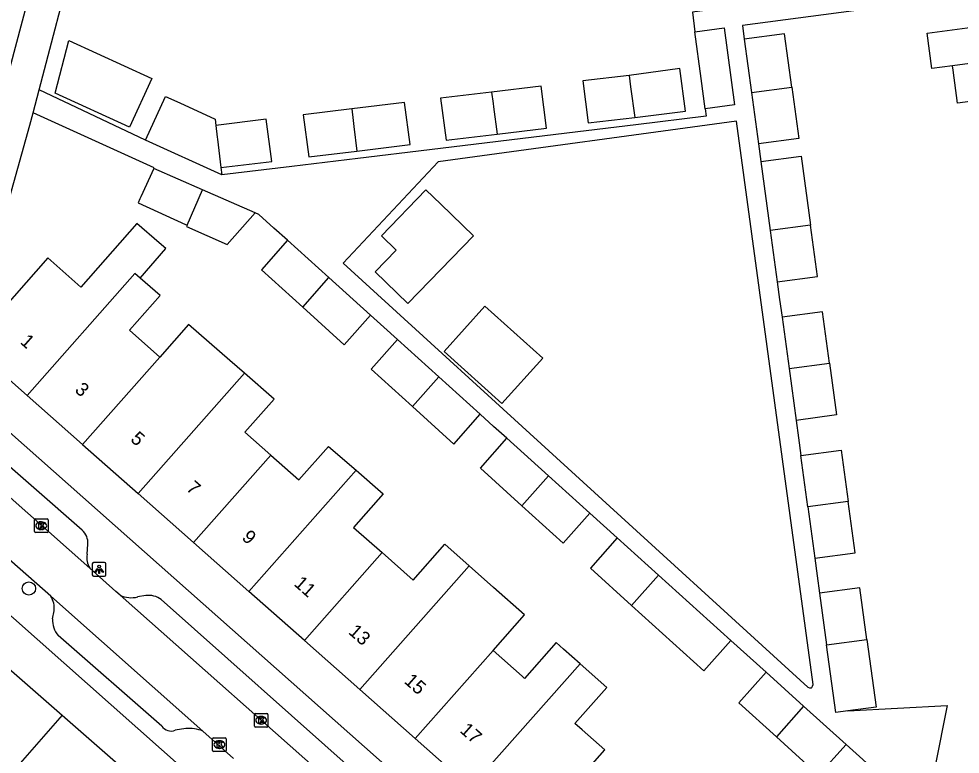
# Model space of a CAD drawing. Extents: x 163150 to 163546, y 380933 to 381635.
# Drawn here: x 163352.4 to 163421.5, y 381091.7 to 381145.6 of the extents above; entities that cross this region are included whole.
import ezdxf

# ---------------------------------------------------------------- set-up
doc = ezdxf.new("R2010")
doc.units = 0
for name, color, linetype in [('IMGEO_Boom', 7, 'Continuous'), ('IMGEO_Erf', 7, 'Continuous'), ('IMGEO_Kolk', 7, 'Continuous'), ('IMGEO_Lichtpunt', 7, 'Continuous'), ('IMGEO_Pand', 7, 'Continuous'), ('IMGEO_Pand_nummerreeks', 7, 'Continuous'), ('IMGEO_Rijbaan_lokaal_open', 7, 'Continuous'), ('IMGEO_Voetpad_open', 7, 'Continuous')]:
    doc.layers.add(name, color=color, linetype=linetype)

msp = doc.modelspace()

# ---------------------------------------------------------------- linework, layer by layer
at = {"layer": 'IMGEO_Boom'}
msp.add_circle((163353.157, 381103.826), 0.489, dxfattribs=at)
at = {"layer": 'IMGEO_Erf'}
msp.add_lwpolyline([(163402.808, 381139.036), (163402.509, 381141.274), (163402.053, 381144.689)], dxfattribs=at)
at = {"layer": 'IMGEO_Kolk'}
for p, q in [((163353.559, 381108.013), (163353.559, 381108.865)), ((163353.634, 381108.939), (163354.486, 381108.939)), ((163354.047, 381108.719), (163354.072, 381108.719)), ((163354.56, 381108.865), (163354.56, 381108.013)), ((163354.486, 381107.939), (163353.634, 381107.939)), ((163354.07, 381108.159), (163354.045, 381108.159)), ((163369.707, 381093.727), (163369.707, 381094.579)), ((163369.782, 381094.653), (163370.634, 381094.653)), ((163370.708, 381094.579), (163370.708, 381093.727)), ((163370.218, 381093.873), (163370.193, 381093.873)), ((163370.195, 381094.433), (163370.22, 381094.433)), ((163370.634, 381093.653), (163369.782, 381093.653)), ((163366.644, 381091.941), (163366.644, 381092.793)), ((163366.719, 381092.867), (163367.571, 381092.867)), ((163367.132, 381092.647), (163367.157, 381092.647)), ((163367.645, 381092.793), (163367.645, 381091.941)), ((163367.571, 381091.867), (163366.719, 381091.867)), ((163367.155, 381092.087), (163367.13, 381092.087))]:
    msp.add_line(p, q, dxfattribs=at)
for points in [[(163353.559, 381108.013), (163353.559, 381108.865)], [(163353.634, 381108.939), (163354.486, 381108.939)], [(163353.88, 381108.639), (163354.003, 381108.639), (163354.003, 381108.488), (163354.133, 381108.639), (163354.297, 381108.639), (163354.151, 381108.488), (163354.304, 381108.239), (163354.152, 381108.239), (163354.067, 381108.403), (163354.003, 381108.336), (163354.003, 381108.239), (163353.88, 381108.239), (163353.88, 381108.639)], [(163354.56, 381108.865), (163354.56, 381108.013)], [(163354.486, 381107.939), (163353.634, 381107.939)], [(163369.707, 381093.727), (163369.707, 381094.579)], [(163369.782, 381094.653), (163370.634, 381094.653)], [(163370.708, 381094.579), (163370.708, 381093.727)], [(163370.028, 381094.353), (163370.151, 381094.353), (163370.151, 381094.202), (163370.281, 381094.353), (163370.445, 381094.353), (163370.299, 381094.202), (163370.452, 381093.953), (163370.3, 381093.953), (163370.215, 381094.117), (163370.151, 381094.05), (163370.151, 381093.953), (163370.028, 381093.953), (163370.028, 381094.353)], [(163370.634, 381093.653), (163369.782, 381093.653)], [(163366.644, 381091.941), (163366.644, 381092.793)], [(163366.719, 381092.867), (163367.571, 381092.867)], [(163366.965, 381092.567), (163367.088, 381092.567), (163367.088, 381092.416), (163367.218, 381092.567), (163367.382, 381092.567), (163367.236, 381092.416), (163367.389, 381092.167), (163367.237, 381092.167), (163367.152, 381092.331), (163367.088, 381092.264), (163367.088, 381092.167), (163366.965, 381092.167), (163366.965, 381092.567)], [(163367.645, 381092.793), (163367.645, 381091.941)], [(163367.571, 381091.867), (163366.719, 381091.867)]]:
    msp.add_lwpolyline(points, dxfattribs=at)
for centre, start, end in [((163353.636, 381108.863), 91.55205, 178.44795), ((163353.636, 381108.863), 91.55205, 178.44795), ((163354.484, 381108.863), 1.55205, 88.44795), ((163354.484, 381108.863), 1.55205, 88.44795), ((163353.636, 381108.015), 181.55205, 268.44795), ((163353.636, 381108.015), 181.55205, 268.44795), ((163354.484, 381108.015), 271.55205, 358.44795), ((163354.484, 381108.015), 271.55205, 358.44795), ((163369.784, 381094.577), 91.55205, 178.44795), ((163369.784, 381094.577), 91.55205, 178.44795), ((163370.632, 381094.577), 1.55205, 88.44795), ((163370.632, 381094.577), 1.55205, 88.44795), ((163369.784, 381093.729), 181.55205, 268.44795), ((163369.784, 381093.729), 181.55205, 268.44795), ((163370.632, 381093.729), 271.55205, 358.44795), ((163370.632, 381093.729), 271.55205, 358.44795), ((163366.721, 381092.791), 91.55205, 178.44795), ((163366.721, 381092.791), 91.55205, 178.44795), ((163367.569, 381092.791), 1.55205, 88.44795), ((163367.569, 381092.791), 1.55205, 88.44795), ((163366.721, 381091.943), 181.55205, 268.44795), ((163366.721, 381091.943), 181.55205, 268.44795), ((163367.569, 381091.943), 271.55205, 358.44795), ((163367.569, 381091.943), 271.55205, 358.44795)]:
    msp.add_arc(centre, 0.0765, start, end, dxfattribs=at)
for centre, major_axis, ratio, start_param, end_param in [((163354.046, 381108.439), (-0.387, 0.002), 0.722429, 4.712389, 7.853982), ((163354.071, 381108.439), (-0.39, 0.002), 0.717154, 1.570796, 4.712389), ((163370.194, 381094.153), (-0.387, 0.002), 0.722429, 4.712389, 7.853982), ((163370.219, 381094.153), (-0.39, 0.002), 0.717154, 1.570796, 4.712389), ((163367.131, 381092.367), (-0.387, 0.002), 0.722429, 4.712389, 7.853982), ((163367.156, 381092.367), (-0.39, 0.002), 0.717154, 1.570796, 4.712389)]:
    msp.add_ellipse(centre, major_axis=major_axis, ratio=ratio, start_param=start_param, end_param=end_param, dxfattribs=at)
at = {"layer": 'IMGEO_Lichtpunt'}
for p, q in [((163357.812, 381105.637), (163357.812, 381104.83)), ((163357.812, 381105.637), (163357.812, 381104.83)), ((163358.714, 381105.732), (163357.906, 381105.732)), ((163358.714, 381105.732), (163357.906, 381105.732)), ((163358.808, 381104.83), (163358.808, 381105.637)), ((163358.808, 381104.83), (163358.808, 381105.637)), ((163357.906, 381104.736), (163358.714, 381104.736)), ((163357.906, 381104.736), (163358.714, 381104.736))]:
    msp.add_line(p, q, dxfattribs=at)
for points in [[(163358.186, 381105.301), (163358.225, 381105.273), (163358.037, 381105.011), (163357.999, 381105.038), (163358.186, 381105.301)], [(163358.288, 381105.253), (163358.335, 381105.253), (163358.335, 381104.931), (163358.288, 381104.931), (163358.288, 381105.253)], [(163358.398, 381105.273), (163358.436, 381105.3), (163358.623, 381105.038), (163358.584, 381105.01), (163358.398, 381105.273)]]:
    msp.add_lwpolyline(points, dxfattribs=at)
msp.add_circle((163358.311, 381105.435), 0.0994, dxfattribs=at)
for centre, start, end in [((163357.906, 381105.637), 90, 180), ((163357.906, 381105.637), 90, 180), ((163358.714, 381105.637), 0, 90), ((163358.714, 381105.637), 0, 90), ((163357.906, 381104.83), 180, 270), ((163357.906, 381104.83), 180, 270), ((163358.714, 381104.83), 270, 0), ((163358.714, 381104.83), 270, 360)]:
    msp.add_arc(centre, 0.0946, start, end, dxfattribs=at)
at = {"layer": 'IMGEO_Pand'}
for points in [[(163420.967, 381142.206), (163419.434, 381142.002), (163419.089, 381144.589), (163423.136, 381145.127), (163422.826, 381147.461)], [(163409.161, 381140.634), (163408.63, 381144.542), (163405.672, 381144.14)], [(163362.192, 381141.257), (163360.544, 381137.68), (163355.083, 381140.179), (163356.085, 381144.052), (163362.192, 381141.257)], [(163405.672, 381144.14), (163406.202, 381140.24)], [(163430.741, 381143.69), (163430.765, 381143.51), (163420.967, 381142.206)], [(163425.72, 381137.678), (163425.411, 381140.001), (163421.332, 381139.458), (163421.009, 381141.888), (163420.967, 381142.206)], [(163397.215, 381141.495), (163393.81, 381141.082), (163394.223, 381137.998), (163397.627, 381138.411)], [(163397.627, 381138.411), (163401.359, 381138.863), (163400.941, 381141.993), (163397.215, 381141.495)], [(163397.215, 381141.495), (163397.328, 381140.647), (163397.627, 381138.411)], [(163387.119, 381140.272), (163383.37, 381139.818), (163383.781, 381136.733), (163387.531, 381137.187)], [(163387.531, 381137.187), (163391.161, 381137.627), (163390.749, 381140.711), (163387.119, 381140.272)], [(163387.119, 381140.272), (163387.232, 381139.424), (163387.262, 381139.196), (163387.531, 381137.187)], [(163406.202, 381140.24), (163409.161, 381140.634)], [(163406.202, 381140.24), (163406.716, 381136.46)], [(163409.161, 381140.634), (163409.675, 381136.854), (163406.716, 381136.46)], [(163361.726, 381136.744), (163363.192, 381139.945), (163364.229, 381139.47), (163366.829, 381138.28), (163366.88, 381137.821)], [(163377.227, 381135.938), (163381.148, 381136.414), (163380.737, 381139.499), (163376.853, 381139.028)], [(163376.853, 381139.028), (163373.291, 381138.597), (163373.703, 381135.511), (163377.227, 381135.938)], [(163376.853, 381139.028), (163376.956, 381138.179), (163377.008, 381137.748), (163377.227, 381135.938)], [(163367.244, 381134.728), (163370.985, 381135.182), (163370.574, 381138.268), (163366.88, 381137.821)], [(163366.88, 381137.821), (163366.975, 381136.97), (163366.993, 381136.804), (163367.244, 381134.728)], [(163367.309, 381134.19), (163361.726, 381136.744)], [(163406.891, 381135.17), (163409.85, 381135.564), (163410.538, 381130.497)], [(163362.332, 381134.664), (163361.378, 381132.572), (163361.311, 381132.426), (163361.177, 381132.131), (163364.663, 381130.54), (163364.767, 381130.493)], [(163365.908, 381133.097), (163362.332, 381134.664)], [(163367.244, 381134.728), (163367.309, 381134.19)], [(163406.891, 381135.17), (163407.579, 381130.103)], [(163364.767, 381130.493), (163365.908, 381133.097)], [(163369.771, 381131.404), (163365.908, 381133.097)], [(163380.971, 381124.745), (163378.57, 381127.072), (163380.121, 381128.672), (163379.036, 381129.725), (163382.304, 381133.096), (163383.39, 381132.043), (163385.791, 381129.715), (163380.971, 381124.745)], [(163364.767, 381130.493), (163364.725, 381130.398), (163367.72, 381129.084), (163369.771, 381131.404)], [(163361.33, 381126.6), (163363.22, 381128.774), (163362.727, 381129.202), (163361.089, 381130.626), (163356.961, 381125.957), (163354.549, 381128.09), (163348.873, 381121.67), (163353.033, 381117.992)], [(163410.538, 381130.497), (163407.579, 381130.103)], [(163408.091, 381126.332), (163411.05, 381126.726), (163410.538, 381130.497)], [(163407.579, 381130.103), (163408.091, 381126.332)], [(163372.142, 381129.385), (163370.238, 381127.231), (163373.266, 381124.483)], [(163375.177, 381126.646), (163372.142, 381129.385)], [(163361.33, 381126.6), (163360.94, 381126.939), (163353.033, 381117.992)], [(163362.776, 381120.816), (163360.539, 381122.793), (163362.785, 381125.334), (163361.33, 381126.6)], [(163373.266, 381124.483), (163375.177, 381126.646)], [(163378.228, 381123.894), (163375.177, 381126.646)], [(163373.266, 381124.483), (163376.309, 381121.722), (163378.228, 381123.894)], [(163390.878, 381120.729), (163387.882, 381117.409), (163383.641, 381121.235), (163386.637, 381124.555), (163390.878, 381120.729)], [(163411.916, 381120.359), (163411.403, 381124.131), (163408.444, 381123.737)], [(163408.444, 381123.737), (163408.957, 381119.965)], [(163368.98, 381119.634), (163367.897, 381120.576), (163364.882, 381123.199), (163362.776, 381120.816)], [(163380.211, 381122.103), (163378.288, 381119.927), (163381.31, 381117.184)], [(163383.241, 381119.369), (163380.211, 381122.103)], [(163362.776, 381120.816), (163357.102, 381114.395)], [(163408.957, 381119.965), (163411.916, 381120.359)], [(163411.916, 381120.359), (163412.431, 381116.565), (163409.472, 381116.171)], [(163361.171, 381110.797), (163368.98, 381119.634)], [(163370.914, 381113.621), (163369.639, 381114.748), (163369.017, 381115.298), (163371.168, 381117.731), (163368.98, 381119.634)], [(163383.241, 381119.369), (163381.31, 381117.184)], [(163386.291, 381116.617), (163383.241, 381119.369)], [(163408.957, 381119.965), (163409.472, 381116.171)], [(163353.033, 381117.992), (163357.102, 381114.395)], [(163381.31, 381117.184), (163384.353, 381114.423), (163386.291, 381116.617)], [(163389.354, 381109.884), (163386.299, 381112.656), (163388.243, 381114.856)], [(163391.306, 381112.092), (163388.243, 381114.856)], [(163357.102, 381114.395), (163361.171, 381110.797)], [(163370.914, 381113.621), (163372.977, 381111.797), (163375.156, 381114.261), (163377.175, 381112.505)], [(163409.823, 381113.586), (163412.782, 381113.98), (163413.293, 381110.222)], [(163365.239, 381107.2), (163370.914, 381113.621)], [(163410.334, 381109.828), (163409.823, 381113.586)], [(163377.175, 381112.505), (163369.307, 381103.603)], [(163377.175, 381112.505), (163379.168, 381110.772), (163376.989, 381108.307), (163379.08, 381106.458)], [(163391.306, 381112.092), (163389.354, 381109.884)], [(163394.328, 381109.364), (163391.306, 381112.092)], [(163361.171, 381110.797), (163365.239, 381107.2)], [(163389.354, 381109.884), (163392.37, 381107.148), (163394.328, 381109.364)], [(163413.293, 381110.222), (163410.334, 381109.828)], [(163410.334, 381109.828), (163410.848, 381106.045)], [(163410.848, 381106.045), (163413.807, 381106.439), (163413.293, 381110.222)], [(163369.307, 381103.603), (163365.239, 381107.2)], [(163379.08, 381106.458), (163381.363, 381104.439), (163383.692, 381107.073), (163385.476, 381105.496)], [(163396.345, 381107.544), (163394.382, 381105.322), (163397.399, 381102.584)], [(163399.37, 381104.814), (163396.345, 381107.544)], [(163379.08, 381106.458), (163373.376, 381100.005)], [(163385.476, 381105.496), (163377.445, 381096.408)], [(163387.229, 381099.277), (163389.545, 381101.898), (163387.267, 381103.912), (163385.476, 381105.496)], [(163397.399, 381102.584), (163399.37, 381104.814)], [(163404.687, 381100.016), (163399.37, 381104.814)], [(163373.376, 381100.005), (163369.307, 381103.603)], [(163414.67, 381100.084), (163414.154, 381103.884), (163411.195, 381103.49)], [(163411.195, 381103.49), (163411.711, 381099.69)], [(163404.687, 381100.016), (163402.696, 381097.778), (163397.399, 381102.584)], [(163377.445, 381096.408), (163373.376, 381100.005)], [(163411.711, 381099.69), (163414.67, 381100.084)], [(163414.67, 381100.084), (163415.344, 381095.127), (163413.276, 381094.847)], [(163393.614, 381098.301), (163392.393, 381099.38), (163391.858, 381099.853), (163389.541, 381097.232), (163389.37, 381097.383), (163387.229, 381099.277)], [(163413.276, 381094.847), (163412.386, 381094.726), (163411.711, 381099.69)], [(163381.514, 381092.81), (163387.229, 381099.277)], [(163351.485, 381098.137), (163355.592, 381094.529)], [(163393.614, 381098.301), (163385.582, 381089.213)], [(163385.582, 381089.213), (163389.741, 381085.536), (163393.054, 381089.282), (163395.432, 381091.972), (163393.769, 381093.442), (163393.233, 381093.916), (163395.576, 381096.566), (163393.614, 381098.301)], [(163407.28, 381097.676), (163405.283, 381095.431), (163408.025, 381092.942)], [(163410.029, 381095.196), (163407.28, 381097.676)], [(163377.445, 381096.408), (163381.514, 381092.81)], [(163410.029, 381095.196), (163408.025, 381092.942)], [(163413.141, 381092.387), (163410.029, 381095.196)], [(163355.592, 381094.529), (163349.921, 381088.076)], [(163355.592, 381094.529), (163359.698, 381090.921)], [(163381.514, 381092.81), (163385.582, 381089.213)], [(163408.025, 381092.942), (163411.13, 381090.125), (163413.141, 381092.387)]]:
    msp.add_lwpolyline(points, dxfattribs=at)
at = {"layer": 'IMGEO_Rijbaan_lokaal_open'}
for points in [[(163354.555, 381152.632), (163353.695, 381149.411), (163353.081, 381147.071), (163351.744, 381141.971), (163350.968, 381139.012), (163349.629, 381133.907), (163348.081, 381128.004), (163346.987, 381123.777)], [(163346.989, 381114.749), (163357.625, 381105.319)], [(163354.767, 381103.254), (163351.292, 381106.335)], [(163359.851, 381103.345), (163359.545, 381103.611), (163357.625, 381105.319)], [(163365.924, 381093.36), (163354.767, 381103.254)], [(163359.851, 381103.345), (163376.424, 381088.651)], [(163368.184, 381091.357), (163365.924, 381093.36)]]:
    msp.add_lwpolyline(points, dxfattribs=at)
at = {"layer": 'IMGEO_Voetpad_open'}
for points in [[(163353.901, 381140.434), (163359.144, 381160.427)], [(163422.826, 381147.461), (163405.534, 381145.153), (163405.672, 381144.14)], [(163403.148, 381146.315), (163401.86, 381146.137), (163402.053, 381144.689)], [(163402.053, 381144.689), (163404.198, 381144.975), (163404.952, 381139.327), (163402.808, 381139.036)], [(163353.46, 381138.753), (163353.901, 381140.434)], [(163361.726, 381136.744), (163353.901, 381140.434)], [(163348.095, 381119.502), (163353.219, 381137.835), (163353.46, 381138.753)], [(163362.332, 381134.664), (163362.354, 381134.712), (163353.46, 381138.753)], [(163402.808, 381139.036), (163402.88, 381138.499), (163397.699, 381137.871), (163392.653, 381137.26), (163387.603, 381136.648), (163382.554, 381136.037), (163377.292, 381135.399), (163372.457, 381134.814), (163367.309, 381134.19)], [(163405.112, 381138.132), (163383.208, 381135.155), (163376.227, 381127.71), (163410.346, 381096.583), (163410.46, 381096.538), (163410.598, 381096.53), (163410.637, 381096.56), (163410.688, 381096.652), (163410.727, 381096.771), (163405.112, 381138.132)], [(163406.716, 381136.46), (163406.891, 381135.17)], [(163372.142, 381129.385), (163371.145, 381130.285), (163370.032, 381131.29), (163369.771, 381131.404)], [(163408.091, 381126.332), (163408.268, 381125.033), (163408.444, 381123.737)], [(163380.211, 381122.103), (163379.209, 381123.008), (163378.228, 381123.894)], [(163348.475, 381118.157), (163412.679, 381061.277)], [(163388.243, 381114.856), (163387.274, 381115.73), (163386.291, 381116.617)], [(163409.472, 381116.171), (163409.645, 381114.895), (163409.823, 381113.586)], [(163357.061, 381108.11), (163349.952, 381114.334)], [(163396.345, 381107.544), (163395.338, 381108.453), (163394.328, 381109.364)], [(163357.428, 381106.34), (163357.477, 381107.075)], [(163410.848, 381106.045), (163411.023, 381104.759), (163411.195, 381103.49)], [(163348.313, 381104.939), (163430.25, 381032.233)], [(163361.739, 381103.306), (163361.141, 381103.213)], [(163377.537, 381089.906), (163377.316, 381090.152), (163362.865, 381103.01)], [(163354.894, 381101.591), (163355.017, 381102.186)], [(163362.905, 381093.729), (163355.295, 381100.367)], [(163407.28, 381097.676), (163404.687, 381100.016)], [(163413.276, 381094.847), (163420.572, 381095.23), (163413.645, 381060.421)], [(163364.667, 381093.538), (163363.904, 381093.422)], [(163415.16, 381090.565), (163414.131, 381091.494), (163413.141, 381092.387)]]:
    msp.add_lwpolyline(points, dxfattribs=at)
for centre, radius, start, end in [((163356.312, 381107.208), 1.173, 353.49692, 50.29666), ((163358.953, 381106.105), 1.543, 171.23367, 210.60814), ((163353.238, 381102.333), 1.785, 355.27992, 31.06952), ((163360.666, 381104.938), 1.789, 242.9141, 285.40093), ((163361.955, 381101.837), 1.485, 52.19338, 98.34956), ((163356.735, 381101.516), 1.842, 177.68074, 218.59834), ((163363.594, 381094.194), 0.831, 213.98045, 291.8544), ((163364.952, 381091.021), 2.533, 67.42781, 96.4524)]:
    msp.add_arc(centre, radius, start, end, dxfattribs=at)

# ---------------------------------------------------------------- texts
at = {"layer": 'IMGEO_Pand_nummerreeks'}
for s, rotation, p in [('1', 318.51786, (163352.464, 381121.858)), ('3', 318.51786, (163356.466, 381118.319)), ('5', 318.51786, (163360.553, 381114.706)), ('7', 318.51786, (163364.64, 381111.093)), ('9', 318.51806, (163368.727, 381107.48)), ('11', 318.51806, (163372.554, 381104.096)), ('13', 318.51806, (163376.556, 381100.558)), ('15', 318.51786, (163380.643, 381096.944)), ('17', 318.51786, (163384.73, 381093.331))]:
    msp.add_text(s, height=1, rotation=rotation, dxfattribs=at).set_placement(p)

doc.saveas('drawing.dxf')
